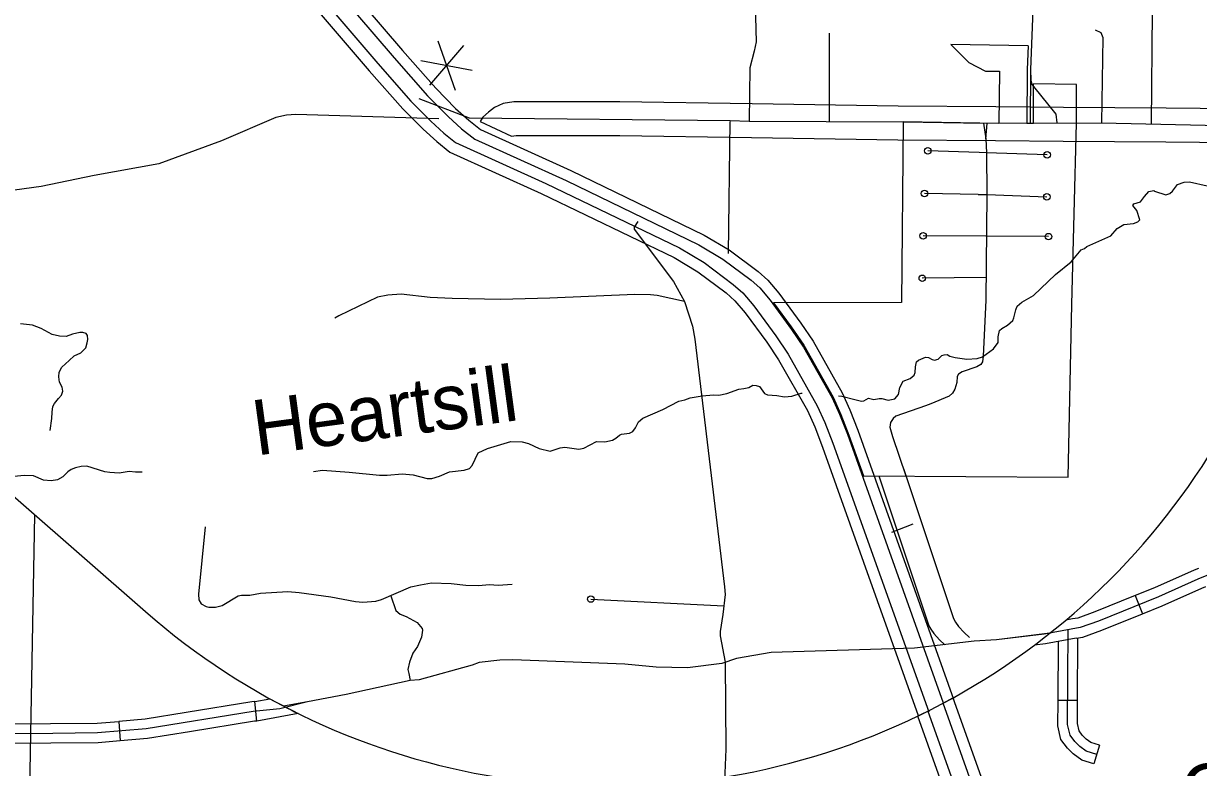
# Model space of a CAD drawing. Extents: x 1370567 to 1373900, y 377514 to 379648.
# Drawn here: x 1372612.6 to 1372869.7, y 378086.8 to 378249.5 of the extents above; entities that cross this region are included whole.
import ezdxf

# ---------------------------------------------------------------- set-up
doc = ezdxf.new("R2010")
doc.units = 0
doc.layers.add('Default', color=7, linetype='Continuous')
doc.layers.add('S_SUBDIV_ANNOT', color=7, linetype='Continuous')

msp = doc.modelspace()

# ---------------------------------------------------------------- linework, layer by layer
at = {"layer": 'Default'}
for p, q in [((1372708.9, 378244.67), (1372701.44, 378236)), ((1372703.29, 378245.73), (1372707.06, 378234.94)), ((1372699.56, 378241.4), (1372710.79, 378239.27)), ((1372855.86, 378124.39), (1372857.47, 378120.42)), ((1372842.92, 378115.06), (1372842.92, 378115.06)), ((1372663.7, 378096.96), (1372663.26, 378101.23)), ((1372843.27, 378101.46), (1372838.98, 378101.48)), ((1372633.46, 378096.88), (1372633.82, 378092.61)), ((1372848.07, 378091.68), (1372846.81, 378087.59))]:
    msp.add_line(p, q, dxfattribs=at)
for points in [[(1372777.23, 378300.74), (1372778.33, 378282.1), (1372778.28, 378281.33), (1372776.7, 378278.76), (1372774.25, 378274.8), (1372772.96, 378271.8), (1372772.51, 378269.49), (1372772.33, 378267.38), (1372772.93, 378245.48), (1372772.5, 378243.48), (1372771.55, 378239.83), (1372771.38, 378228.13)], [(1372672.37, 378266.95), (1372693.75, 378241.99), (1372701.05, 378233.67), (1372705.52, 378229.18), (1372708.49, 378226.49), (1372711.35, 378224.2), (1372731.37, 378215.14), (1372760.42, 378201.1), (1372765.66, 378197.99), (1372771.82, 378193.37), (1372773.74, 378191.66), (1372775.97, 378189.02), (1372780.7, 378182.59), (1372783.31, 378178.73), (1372789.59, 378167.63), (1372791.18, 378164.09), (1372792.91, 378159.68), (1372813.85, 378100.96)], [(1372674.21, 378268.54), (1372695.58, 378243.58), (1372702.83, 378235.33), (1372707.19, 378230.94), (1372710.06, 378228.34), (1372712.63, 378226.29), (1372732.4, 378217.34), (1372761.57, 378203.24), (1372767.01, 378200.01), (1372773.36, 378195.26), (1372775.49, 378193.36), (1372777.88, 378190.52), (1372782.68, 378183.99), (1372785.38, 378180.02), (1372791.76, 378168.73), (1372793.43, 378165.03), (1372795.18, 378160.53), (1372816.14, 378101.77)], [(1372666.92, 378264.15), (1372688.3, 378239.18), (1372695.61, 378230.86), (1372700.07, 378226.37), (1372703.04, 378223.68), (1372705.9, 378221.39), (1372725.92, 378212.33), (1372754.97, 378198.29), (1372760.21, 378195.18), (1372766.37, 378190.57), (1372768.29, 378188.86), (1372770.52, 378186.21), (1372775.25, 378179.78), (1372777.86, 378175.93), (1372784.15, 378164.83), (1372785.74, 378161.28), (1372787.46, 378156.87), (1372808.4, 378098.15)], [(1372668.76, 378265.73), (1372690.13, 378240.77), (1372697.38, 378232.52), (1372701.75, 378228.13), (1372704.62, 378225.53), (1372707.18, 378223.48), (1372726.95, 378214.53), (1372756.13, 378200.44), (1372761.56, 378197.2), (1372767.91, 378192.45), (1372770.04, 378190.56), (1372772.43, 378187.72), (1372777.23, 378181.18), (1372779.93, 378177.21), (1372786.32, 378165.92), (1372787.98, 378162.22), (1372789.74, 378157.72), (1372810.69, 378098.97)], [(1372831.94, 378264.28), (1372833.14, 378262.17), (1372833.91, 378259.54), (1372834.05, 378258.57), (1372833.57, 378254.29), (1372832.93, 378239.42), (1372833.05, 378237.1), (1372833.27, 378236.13), (1372833.64, 378235.69)], [(1372477.32, 378262.49), (1372639.33, 378120.88)], [(1372859.55, 378252.21), (1372859.33, 378227.52)], [(1372788.9, 378247.37), (1372788.9, 378228.04)], [(1372847.12, 378248.14), (1372848.35, 378247.51), (1372848.78, 378246.43), (1372848.49, 378227.79)], [(1372832.44, 378244.58), (1372815.55, 378244.87), (1372819.49, 378241), (1372823.08, 378239.04), (1372826.15, 378239.04), (1372826, 378227.62), (1372805.12, 378227.96), (1372804.74, 378188.48), (1372776.76, 378188.4)], [(1372832.44, 378244.58), (1372832.22, 378239.43), (1372832.18, 378227.72), (1372833.61, 378227.72), (1372833.64, 378236.32)], [(1372832.93, 378239.42), (1372832.9, 378227.84)], [(1372843.04, 378227.73), (1372843.04, 378236.18), (1372833.64, 378236.32)], [(1372833.64, 378235.69), (1372838.47, 378229.68), (1372838.72, 378227.74)], [(1372699.13, 378233.12), (1372710.14, 378228.88), (1372767.24, 378228.3), (1372771.38, 378228.13), (1372805.12, 378227.96), (1372822.66, 378227.68)], [(1372703.54, 378228.67), (1372672.2, 378229.57), (1372670.18, 378229.48), (1372667.84, 378228.91), (1372655.99, 378223.81), (1372642.28, 378218.8), (1372628.09, 378216.27), (1372616.47, 378213.88), (1372604.28, 378212.17), (1372599.6, 378211.81), (1372592.52, 378210.44), (1372588.24, 378209.99), (1372583.41, 378209.76), (1372576.82, 378209.11), (1372556.84, 378208.41), (1372539.58, 378208.07)], [(1372703.54, 378228.67), (1372672.2, 378229.57), (1372670.18, 378229.48), (1372667.84, 378228.91), (1372655.99, 378223.81), (1372642.28, 378218.8), (1372628.09, 378216.27), (1372616.47, 378213.88), (1372604.28, 378212.17)], [(1372766.88, 378199.23), (1372767.24, 378228.09)], [(1372796.4, 378150.61), (1372841.18, 378150.29), (1372842.01, 378188.05), (1372843.04, 378227.73)], [(1372822.66, 378227.68), (1372848.49, 378227.79), (1372871.21, 378227.23), (1372895.4, 378227.14)], [(1372822.66, 378227.68), (1372823.22, 378224.29), (1372823.48, 378227.66)], [(1372823.22, 378224.29), (1372823.36, 378221.24), (1372823.42, 378212.08), (1372823.18, 378188.96)], [(1372821.71, 378221.3), (1372810.47, 378221.64)], [(1372836.61, 378220.77), (1372823.36, 378221.24), (1372821.71, 378221.3)], [(1372845.25, 378200.71), (1372850.52, 378203.05), (1372851.89, 378204.67), (1372853.4, 378205.53), (1372855.49, 378205.78), (1372856.46, 378206.1), (1372856.86, 378206.55), (1372856.2, 378208.58), (1372855.32, 378209.69), (1372855.57, 378210.04), (1372857.06, 378210.49), (1372857.91, 378211.66), (1372858.86, 378212.72), (1372859.91, 378212.97), (1372860.06, 378212.83), (1372862.54, 378212.03), (1372863.48, 378212.29), (1372864.02, 378212.8), (1372865.14, 378214.28), (1372866.59, 378214.8), (1372867.76, 378214.85), (1372871.62, 378214.03), (1372874.82, 378213.56)], [(1372821.53, 378212.11), (1372809.76, 378212.3)], [(1372821.53, 378212.11), (1372823.42, 378212.08), (1372836.55, 378211.61)], [(1372747.08, 378206.22), (1372746.22, 378204.94), (1372746.28, 378204.54), (1372754.87, 378193.11), (1372757.27, 378188.72), (1372759.01, 378183.29), (1372759.55, 378180.49), (1372766.04, 378126.31), (1372766.13, 378124.6), (1372765.67, 378120.26), (1372765.07, 378116.52), (1372765.04, 378115.58), (1372766.19, 378109.82)], [(1372747.08, 378206.22), (1372746.22, 378204.94), (1372746.28, 378204.54), (1372754.87, 378193.11), (1372757.27, 378188.72), (1372759.01, 378183.29), (1372759.55, 378180.49), (1372766.04, 378126.31), (1372766.13, 378124.6), (1372765.67, 378120.26), (1372765.07, 378116.52), (1372765.04, 378115.58), (1372766.19, 378109.82)], [(1372836.91, 378202.89), (1372809.45, 378203.04)], [(1372829.75, 378186.9), (1372830.06, 378187.67), (1372831.06, 378188.55), (1372833.63, 378190.03), (1372838.46, 378194.57), (1372841.83, 378197.36), (1372844.03, 378199.99), (1372844.74, 378200.3), (1372845.25, 378200.71)], [(1372823.23, 378193.94), (1372809.29, 378193.78)], [(1372757.27, 378188.72), (1372751.27, 378189.98), (1372749.82, 378190.18), (1372746.42, 378190.24), (1372727.83, 378189.45), (1372716.98, 378189.17), (1372706.39, 378189.35), (1372701.6, 378189.61), (1372695.29, 378190.3), (1372692.32, 378190.12), (1372690.12, 378189.65), (1372681.64, 378185.54), (1372680.73, 378185.06)], [(1372776.76, 378188.4), (1372780.63, 378183.14), (1372783.35, 378179.13), (1372789.78, 378167.77), (1372791.47, 378164), (1372793.24, 378159.47), (1372796.4, 378150.61)], [(1372823.18, 378188.96), (1372822.63, 378176.75), (1372822.47, 378175.49), (1372822.08, 378174.94), (1372821.22, 378174.39), (1372818, 378173.29), (1372817.22, 378172.82), (1372816.9, 378172.27), (1372816.83, 378171.02), (1372816.43, 378169.53), (1372815.88, 378168.66), (1372815.18, 378168.03), (1372811.18, 378166.31), (1372810.02, 378165.9)], [(1372790.93, 378168.05), (1372791.69, 378168), (1372794.54, 378167.28), (1372795.97, 378166.91), (1372796.48, 378166.99), (1372797.51, 378167.54), (1372798.65, 378167.25), (1372799.85, 378167.48), (1372800.4, 378167.48), (1372801.82, 378167.13), (1372803.28, 378167.42), (1372804.08, 378168.39), (1372804.39, 378169.87), (1372805.11, 378171.3), (1372806.65, 378171.87), (1372807.48, 378172.58), (1372807.73, 378173.15), (1372807.82, 378174.44), (1372808.05, 378175.49), (1372808.48, 378175.89), (1372810.02, 378176.55), (1372810.65, 378176.49), (1372811.45, 378176), (1372811.93, 378175.86), (1372812.73, 378176.12), (1372813.59, 378176.86), (1372814.1, 378177.06), (1372814.7, 378177.09), (1372815.3, 378176.77), (1372816.47, 378176.46), (1372819.01, 378176.08), (1372821.27, 378176.2), (1372822.44, 378176.62), (1372824.86, 378178.36), (1372825.86, 378179.76), (1372825.89, 378180.96), (1372826.21, 378182.39), (1372826.66, 378182.82), (1372827.95, 378183.56), (1372829.12, 378184.58), (1372829.35, 378185.15), (1372829.75, 378186.9)], [(1372618.5, 378160.52), (1372618.85, 378163.11), (1372618.91, 378164.52), (1372619.09, 378165.76), (1372619.44, 378166.41), (1372620.32, 378167.47), (1372620.97, 378168.23), (1372621.21, 378169.12), (1372621.09, 378170), (1372620.5, 378171.06), (1372620.38, 378172.24), (1372620.44, 378173.24), (1372621.03, 378174.36), (1372622.62, 378175.77), (1372623.74, 378176.83), (1372625.21, 378177.48), (1372626.27, 378178.54), (1372626.56, 378179.66), (1372626.74, 378180.37), (1372626.62, 378181.25), (1372626.33, 378181.67), (1372625.62, 378181.9), (1372624.97, 378181.9), (1372623.38, 378181.55), (1372621.97, 378181.08), (1372620.5, 378181.14), (1372618.91, 378181.49), (1372616.5, 378182.79), (1372614.61, 378183.49), (1372611.98, 378183.85)], [(1372761.1, 378168.07), (1372763.61, 378168.28), (1372764.77, 378168.24), (1372766.51, 378168.56), (1372769.14, 378169.55), (1372770.25, 378169.7), (1372771.33, 378169.87), (1372772.22, 378170.44)], [(1372772.22, 378170.44), (1372772.96, 378170.35), (1372773.68, 378170.09), (1372774.76, 378168.61), (1372775.42, 378168.32), (1372777.44, 378168.15), (1372779.13, 378167.86), (1372780.75, 378168.03), (1372782.81, 378168.69), (1372783, 378168.68)], [(1372676.06, 378151.55), (1372678.06, 378151.78), (1372683.89, 378151.4), (1372690.54, 378150.71), (1372692.19, 378150.71), (1372695.48, 378151.02), (1372697.87, 378150.82), (1372700.99, 378149.96), (1372702.01, 378150.02), (1372703.67, 378150.5), (1372705.84, 378151.47), (1372709.04, 378151.78), (1372710.21, 378152.21), (1372710.78, 378152.87), (1372712.15, 378155.58), (1372714.15, 378156.58), (1372719.26, 378158.09), (1372721.74, 378158), (1372723.11, 378157.63), (1372725.48, 378156.57), (1372727.85, 378156), (1372730.02, 378156.68), (1372731.05, 378156.82), (1372734.13, 378156.39), (1372735.22, 378156.62), (1372737.99, 378158.1), (1372739.84, 378158.04), (1372741.47, 378158.36), (1372742.27, 378158.78), (1372743.01, 378159.44), (1372743.44, 378159.67), (1372745.21, 378159.92), (1372745.98, 378160.29), (1372746.55, 378161.06), (1372747.18, 378162.4), (1372748.15, 378163.2), (1372752.52, 378165.11), (1372756, 378166.94), (1372757.32, 378167.19), (1372758.48, 378167.61), (1372761.1, 378168.07)], [(1372810.02, 378165.9), (1372803.51, 378163.61), (1372802.88, 378163.14), (1372802.33, 378162.27), (1372802.17, 378161.25), (1372802.8, 378159.21), (1372805.69, 378150.55)], [(1372638.61, 378151.35), (1372637.15, 378151.35), (1372635.78, 378151.55), (1372633.56, 378151.15), (1372631.5, 378151.3), (1372630.44, 378151.47), (1372626.51, 378152.67), (1372625.22, 378152.64), (1372623.99, 378152.36), (1372623.05, 378151.96), (1372622.31, 378151.45), (1372621.22, 378150.39), (1372620.05, 378149.73), (1372618.68, 378149.48), (1372617.03, 378149.62), (1372614.83, 378150.54), (1372612.8, 378150.65), (1372600.98, 378149.46)], [(1372805.18, 378152.18), (1372816.1, 378119.39), (1372816.57, 378118.6), (1372817.2, 378117.66), (1372818.46, 378116.33), (1372819.64, 378115.24)], [(1372799.78, 378150.59), (1372810.71, 378117.8), (1372811.18, 378117.01), (1372811.8, 378116.07), (1372813.06, 378114.74), (1372814.24, 378113.65)], [(1372615.07, 378142.08), (1372614.16, 378094.19), (1372613.23, 378040.47), (1372612.68, 378016.76)], [(1372652.37, 378139.43), (1372650.91, 378124.71), (1372651.01, 378123.46), (1372651.53, 378122.59), (1372652.62, 378121.99), (1372653.19, 378121.85), (1372654.64, 378121.88), (1372656.07, 378122.19), (1372659.58, 378124.33), (1372660.33, 378124.5), (1372662.15, 378124.47), (1372664.47, 378124.93), (1372670.49, 378125.26), (1372672.97, 378125.06), (1372679.91, 378124.14), (1372685.25, 378123.11), (1372686.85, 378122.94), (1372689.76, 378123.17), (1372690.96, 378123.51), (1372697.41, 378126.27), (1372699.52, 378126.76), (1372701.92, 378127.15), (1372706.18, 378127.04), (1372709.4, 378126.66), (1372712.2, 378126.6), (1372714.57, 378126.8), (1372716.48, 378126.66), (1372719.54, 378126.91)], [(1372807.24, 378139.97), (1372802.53, 378138.22)], [(1372879.41, 378132), (1372869.58, 378127.95), (1372860.93, 378124.13), (1372847.83, 378118.83), (1372843.86, 378117.41), (1372835.92, 378115.98), (1372825.53, 378114.71), (1372820.65, 378114.4), (1372807.55, 378112.86), (1372776.23, 378111.92), (1372768.6, 378110.6), (1372765.41, 378109.55), (1372757.9, 378108.56), (1372751.08, 378108.74), (1372744.22, 378109.37), (1372719.7, 378110.33), (1372716.85, 378110.27), (1372712.34, 378109.76), (1372710.77, 378109.19), (1372699.18, 378105.98), (1372697.23, 378105.81), (1372683.24, 378102.73), (1372674.74, 378101.14), (1372668.71, 378099.63), (1372662.89, 378099.04), (1372639.51, 378095.23), (1372628.86, 378094.35), (1372614.16, 378094.19), (1372603.74, 378094.34)], [(1372869.72, 378130.32), (1372868.74, 378129.92), (1372860.1, 378126.1), (1372855.86, 378124.39)], [(1372857.47, 378120.42), (1372861.77, 378122.16), (1372870.43, 378125.98), (1372871.35, 378126.36)], [(1372692.99, 378124.33), (1372694.13, 378121.11), (1372695.07, 378120.31), (1372696.38, 378119.79), (1372698.75, 378118.51), (1372699.83, 378117.22), (1372699.92, 378116.82), (1372699.72, 378115.31), (1372698.83, 378113.28), (1372697.83, 378111.8), (1372697.06, 378109.8), (1372696.75, 378108.26), (1372696.95, 378107.35), (1372697.23, 378105.81)], [(1372736.76, 378123.63), (1372765.86, 378122.12)], [(1372855.86, 378124.39), (1372847.06, 378120.83), (1372843.3, 378119.48), (1372842.17, 378119.28)], [(1372842.92, 378115.06), (1372844.41, 378115.33), (1372848.59, 378116.83), (1372857.47, 378120.42)], [(1372842.17, 378119.28), (1372840.69, 378119.01)], [(1372837.16, 378116.14), (1372825.53, 378114.71), (1372820.65, 378114.4), (1372807.55, 378112.86), (1372776.23, 378111.92), (1372768.6, 378110.6), (1372765.41, 378109.55), (1372757.9, 378108.56), (1372751.08, 378108.74), (1372744.22, 378109.37), (1372719.7, 378110.33), (1372716.85, 378110.27), (1372712.34, 378109.76), (1372710.77, 378109.19), (1372699.18, 378105.98), (1372697.23, 378105.81), (1372683.24, 378102.73), (1372674.74, 378101.14), (1372669.55, 378100.22)], [(1372842.92, 378115.06), (1372836.24, 378113.86), (1372833.83, 378113.57)], [(1372847.44, 378089.63), (1372845.15, 378090.34), (1372843.74, 378091.4), (1372842.68, 378092.46), (1372841.62, 378093.87), (1372841.09, 378096.17), (1372841.22, 378116.93)], [(1372843.27, 378101.46), (1372843.35, 378115.14)], [(1372838.98, 378101.48), (1372839.06, 378114.37)], [(1372766.19, 378109.82), (1372766.32, 378090.8), (1372766.11, 378085.52), (1372766.08, 378079.35), (1372764.54, 378058.89), (1372764.02, 378054.69), (1372764.14, 378053.67), (1372764.45, 378052.81), (1372765.15, 378051.63), (1372766.3, 378048.67), (1372767.22, 378045.24), (1372767.16, 378043.33), (1372766.7, 378042.27), (1372765.64, 378040.99), (1372764.19, 378039.76), (1372761.39, 378038.05), (1372750.2, 378033.12), (1372749.34, 378032.26), (1372747.11, 378027.84), (1372741.37, 378020.14)], [(1372766.19, 378109.82), (1372766.32, 378090.8), (1372766.11, 378085.52), (1372766.11, 378084.71)], [(1372663.26, 378101.23), (1372662.61, 378101.16), (1372648.24, 378098.82)], [(1372663.26, 378101.23), (1372666.55, 378101.83)], [(1372813.84, 378100.85), (1372816, 378102.03), (1372842.34, 378028.17), (1372843.95, 378023.97), (1372849.75, 378007.47), (1372852.25, 377999.64), (1372854.78, 377988.5), (1372855.98, 377980.29), (1372867.18, 377886.4)], [(1372864.76, 377886.12), (1372853.57, 377979.97), (1372852.39, 377988.06), (1372849.9, 377999), (1372847.44, 378006.7), (1372841.66, 378023.13), (1372840.07, 378027.33), (1372813.84, 378100.85)], [(1372846.81, 378087.59), (1372844.16, 378088.4), (1372842.33, 378089.78), (1372841.06, 378091.05), (1372839.63, 378092.95), (1372838.95, 378095.93), (1372838.98, 378101.48)], [(1372848.07, 378091.68), (1372846.14, 378092.28), (1372845.15, 378093.02), (1372844.3, 378093.87), (1372843.61, 378094.8), (1372843.23, 378096.41), (1372843.27, 378101.46)], [(1372648.24, 378098.82), (1372639.25, 378097.36), (1372633.46, 378096.88)], [(1372672.74, 378098.6), (1372663.7, 378096.96)], [(1372808.32, 378098.05), (1372810.51, 378099.13), (1372836.58, 378026.05), (1372838.18, 378021.86), (1372843.92, 378005.52), (1372846.31, 377998.02), (1372848.73, 377987.38), (1372849.89, 377979.48), (1372861.08, 377885.68)], [(1372858.66, 377885.39), (1372847.48, 377979.16), (1372846.34, 377986.93), (1372843.97, 377997.38), (1372841.62, 378004.74), (1372835.9, 378021.02), (1372834.3, 378025.21), (1372808.32, 378098.05)], [(1372603.47, 378096.48), (1372603.74, 378096.48), (1372614.16, 378096.33), (1372618.55, 378096.38)], [(1372618.55, 378096.38), (1372628.76, 378096.49), (1372633.46, 378096.88)], [(1372648.93, 378094.59), (1372639.77, 378093.1), (1372633.82, 378092.61)], [(1372663.7, 378096.96), (1372663.17, 378096.91), (1372648.93, 378094.59)], [(1372618.59, 378092.09), (1372614.15, 378092.05), (1372603.73, 378092.2), (1372603.5, 378092.19)], [(1372633.82, 378092.61), (1372628.96, 378092.21), (1372618.59, 378092.09)]]:
    msp.add_lwpolyline(points, dxfattribs=at)
for centre in [(1372810.47, 378221.64), (1372836.61, 378220.77), (1372809.76, 378212.3), (1372836.55, 378211.61), (1372809.45, 378203.04), (1372836.91, 378202.89), (1372809.29, 378193.78), (1372736.76, 378123.63)]:
    msp.add_circle(centre, 0.714, dxfattribs=at)
for centre, radius, start, end in [((1372741.09, 378237.31), 154.64, 228.844, 356.8229), ((1372741.07, 378237.26), 154.58, 241.1801, 243.7673)]:
    msp.add_arc(centre, radius, start, end, dxfattribs=at)
at = {"layer": 'S_SUBDIV_ANNOT'}
for points in [[(1372899.73, 378230.59), (1372862.62, 378230.98), (1372840.19, 378231.16), (1372825.37, 378231.3), (1372804.04, 378231.44), (1372772.05, 378231.92), (1372743.14, 378232.35), (1372719.89, 378232.35), (1372717.59, 378232.03), (1372715.72, 378231.12), (1372714.36, 378230.13), (1372713.13, 378228.98), (1372712.53, 378228.1), (1372719.44, 378224.85)], [(1372719.44, 378224.85), (1372720.41, 378224.98), (1372743.09, 378224.98), (1372771.94, 378224.55), (1372803.96, 378224.07), (1372825.32, 378223.93), (1372840.12, 378223.79), (1372862.56, 378223.61), (1372899.42, 378223.22), (1372899.65, 378223.22), (1372899.73, 378230.59)]]:
    msp.add_lwpolyline(points, dxfattribs=at)

# ---------------------------------------------------------------- texts
at = {"layer": 'Default'}
for s, rotation, p in [('Heartsill', 7.7028, (1372663.59, 378154.99)), ('Creek', 6.6441, (1372866.64, 378074.9))]:
    msp.add_text(s, height=12.069, rotation=rotation, dxfattribs=at).set_placement(p)

doc.saveas('drawing.dxf')
